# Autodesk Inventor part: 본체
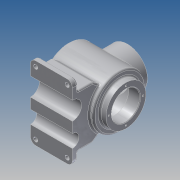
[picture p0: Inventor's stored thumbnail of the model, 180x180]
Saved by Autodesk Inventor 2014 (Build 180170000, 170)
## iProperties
Created: 2018-08
Part Number: 본체
Material: 알루미늄 6061
Document SubType Name: Modeling
Designer: kb542
Density: 2.71 g/cm^3
Appearance: 알루미늄 - 평지
Mass: 1886.05 g
Surface Area: 1087.39 cm^2
Volume: 695.96 cm^3
Author: kb542
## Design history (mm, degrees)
sketch "스케치1"
  geometry: L1 (0, 0)-(120, 0); L2 (0, 27)-(22, 27); L3 (22, 27)-(22, 37); L4 (25, 40)-(100.125, 40); L5 (0, 27)-(0, 38); L6 (0, 38)-(12, 38); L7 (12, 38)-(12, 50); L8 (12, 50)-(108.671, 50); A1 r 116 centre (4, 0) between (120, 0) and (108.671, 50); A2 r 106 centre (4, 0) between (110, 0) and (102.925, 38.078); A3 r 3 centre (25, 37) between (25, 40) and (22, 37); A4 r 3 centre (100.125, 37) between (102.925, 38.078) and (100.125, 40); 2 further points
  constraints: 16 end point, 9 point on circle, 4 centre point, 4 parallel, 4 point on line, 4 tangent, 3 perpendicular, 1 coincident, 1 equal radius, 1 horizontal, 1 horizontal alignment, 1 vertical alignment
  dimensions: "d17" = 120 distance of L1.start L1.end; "d18" = 116 radius of A1; "d20" = 108 distance from line of L7 L1.end; "d21" = 100 diameter of L8 L1; "d22" = 76 diameter of L6 L1; "d23" = 54 diameter of L2 L1; "d24" = 22 distance of L2.start L2.end; "d25" = 80 diameter of L4 L1; "d26" = 10 radial gap between concentric circles of A1 A2; "d78" = 3 radius of A3
revolve "회전2" sketch "스케치1" stored, may be unused: angle "d27" = 90 deg
node "작업 평면3"
sketch "스케치3"
  geometry: L1 (-70, -72)-(70, -72); L2 (70, -72)-(70, -82); L3 (70, -82)-(-70, -82); L4 (-70, -82)-(-70, -72); 2 further points
  constraints: 8 end point, 2 parallel, 1 horizontal, 1 midpoint, 1 perpendicular, 1 vertical alignment
  dimensions: "d29" = 82 distance from line of L3 point (0, 0); "d30" = 10 distance of L1.end L2.end; "d31" = 140 distance of L2.end L3.end
extrude "돌출2" join sketch "스케치3" distance "d32" = 80; taper "d33" = 0 deg
node "작업 평면4"
sketch "스케치4"
  geometry: L1 (-70, -72)-(70, -72) reference; L2 (0, 0)-(0, -72); L3 (-70, -82)-(-70, -72) reference; L4 (-50, -72)-(-50, -43.437); L5 (-50, -43.437)-(-40.304, -29.59); L6 (50, -43.437)-(40.304, -29.59); L7 (50, -72)-(50, -43.437); L8 (-50, -72)-(50, -72); L9 (-50, -43.437)-(-70, -72); A1 r 50 centre (0, 0) between (-40.304, -29.59) and (40.304, -29.59); 1 further point
  constraints: 14 end point, 3 symmetric about line, 2 collinear, 2 point on circle, 1 centre point, 1 midpoint, 1 parallel, 1 point on line, 3 other
  dimensions: "d37" = 20 distance between parallel lines of L3 L4; "d38" = 35 deg angle of L3 L5
extrude "돌출3" join sketch "스케치4" stored distance "d39" = 80; taper "d40" = 0 deg
sketch "스케치5"
  geometry: L1 (-70, -82)-(70, -82) reference; L2 (0, 0)-(0, -82); L3 (-70, -82)-(70, -82) reference; C1 r 50 at (0, 0) reference; C2 r 12.5 at (-27.5, -82); C3 r 17.5 at (22.5, -82)
  constraints: 2 centre point, 2 end point, 2 point on line, 1 midpoint
  dimensions: "d41" = 27.5 distance from line of C2.centre L2; "d42" = 22.5 distance from line of C3.centre L2; "d44" = 12.5 radius of C2; "d45" = 17.5 radius of C3
extrude "돌출4" cut sketch "스케치5" stored distance "d46" = 80; taper "d47" = 0 deg
node "작업 평면5"
sketch "스케치6"
  geometry: L1 (-88, 20)-(-88, 120) reference; C1 r 38 at (-38, 70); 1 further point
  constraints: 1 centre point, 1 horizontal alignment
  dimensions: "d49" = 76 diameter of C1; "d50" = 50 distance from line of L1 C1.centre
extrude "돌출5" join sketch "스케치6" stored distance "d51" = 80; taper "d52" = 0 deg
sketch "스케치7"
  geometry: C1 r 38 at (0, 0) reference; C2 r 27 at (0, 0); 1 further point
  constraints: 1 centre point, 1 coincident
  dimensions: "d53" = 54 diameter of C2
extrude "돌출6" cut sketch "스케치7" stored distance "d54" = 80; taper "d55" = 0 deg
sketch "스케치8" dims "d56" = 65
  geometry: C1 r 27 at (0, 0) reference; C2 r 38 at (0, 0) reference; 3 further points
  constraints: 2 horizontal alignment, 1 coincident, 2 other
hole "구멍1" sketch "스케치8" at (-32.5, 0) diameter "d57" = 3.242; stored, may be unused: countersink angle "d61" = 90 deg, drill point angle "d63" = 118 deg; dims "d58" = 8, "d59" = 4, "d60" = 2, "d62" = 10
sketch "스케치9" dims "d67" = 65
  geometry: C1 r 38 at (0, 0) reference; C2 r 27 at (0, 0) reference; 2 further points
  constraints: 2 vertical alignment, 1 coincident, 2 other
hole "구멍2" sketch "스케치9" at (0, 32.5) diameter "d68" = 3.242; stored, may be unused: countersink angle "d72" = 90 deg, drill point angle "d74" = 118 deg; dims "d69" = 8, "d70" = 4, "d71" = 2, "d73" = 10
fillet "모깎기1" dims "d79" = 10
hole "구멍3" diameter "d82" = 8; stored, may be unused: countersink angle "d86" = 90 deg, drill point angle "d88" = 118 deg; dims "d80" = 10, "d81" = 10, "d83" = 8, "d84" = 4, "d85" = 2, "d87" = 10
hole "구멍4" diameter "d91" = 8; stored, may be unused: countersink angle "d95" = 90 deg, drill point angle "d97" = 118 deg; dims "d89" = 10, "d90" = 10, "d92" = 8, "d93" = 4, "d94" = 2, "d96" = 10
hole "구멍5" diameter "d100" = 8; stored, may be unused: countersink angle "d104" = 90 deg, drill point angle "d106" = 118 deg; dims "d98" = 10, "d99" = 10, "d101" = 8, "d102" = 4, "d103" = 2, "d105" = 10
hole "구멍6" diameter "d109" = 8; stored, may be unused: countersink angle "d113" = 90 deg, drill point angle "d115" = 118 deg; dims "d107" = 10, "d108" = 10, "d110" = 8, "d111" = 4, "d112" = 2, "d114" = 10
chamfer "모따기1" distance "d116" = 1; stored, may be unused: second distance "d117" = 2, angle "d118" = 45 deg
chamfer "모따기2" distance "d119" = 1; stored, may be unused: second distance "d120" = 2, angle "d121" = 45 deg
fillet "모깎기2" dims "d122" = 3
fillet "모깎기3" dims "d123" = 3
fillet "모깎기4" dims "d124" = 3
fillet "모깎기5" dims "d125" = 3
fillet "모깎기6" dims "d126" = 3
fillet "모깎기7" dims "d127" = 3
fillet "모깎기8" dims "d128" = 3
node "작업 평면6"
sketch "스케치10"
  geometry: C1 r 32.5 at (0, 0); 1 further point
  constraints: 1 centre point, 1 coincident, 1 other
  dimensions: "d130" = 65 diameter of C1
feature "엠보싱1" sketch "스케치10" dims "d17" = 120, "d18" = 116, "d20" = 108, "d21" = 100, "d22" = 76, "d23" = 54, "d24" = 22, "d25" = 80, "d26" = 10, "d29" = 82, "d78" = 3, "d131" = 0.5, "d132" = 0
fillet "모깎기9" dims "d133" = 3
node "솔리드2"
pattern_circular "원형 패턴1" dims angle "d65" = 360 deg
pattern_circular "원형 패턴2" dims angle "d76" = 360 deg
other parameters: "d28" = -8, "d48" = -147, "d129" = -131.5
